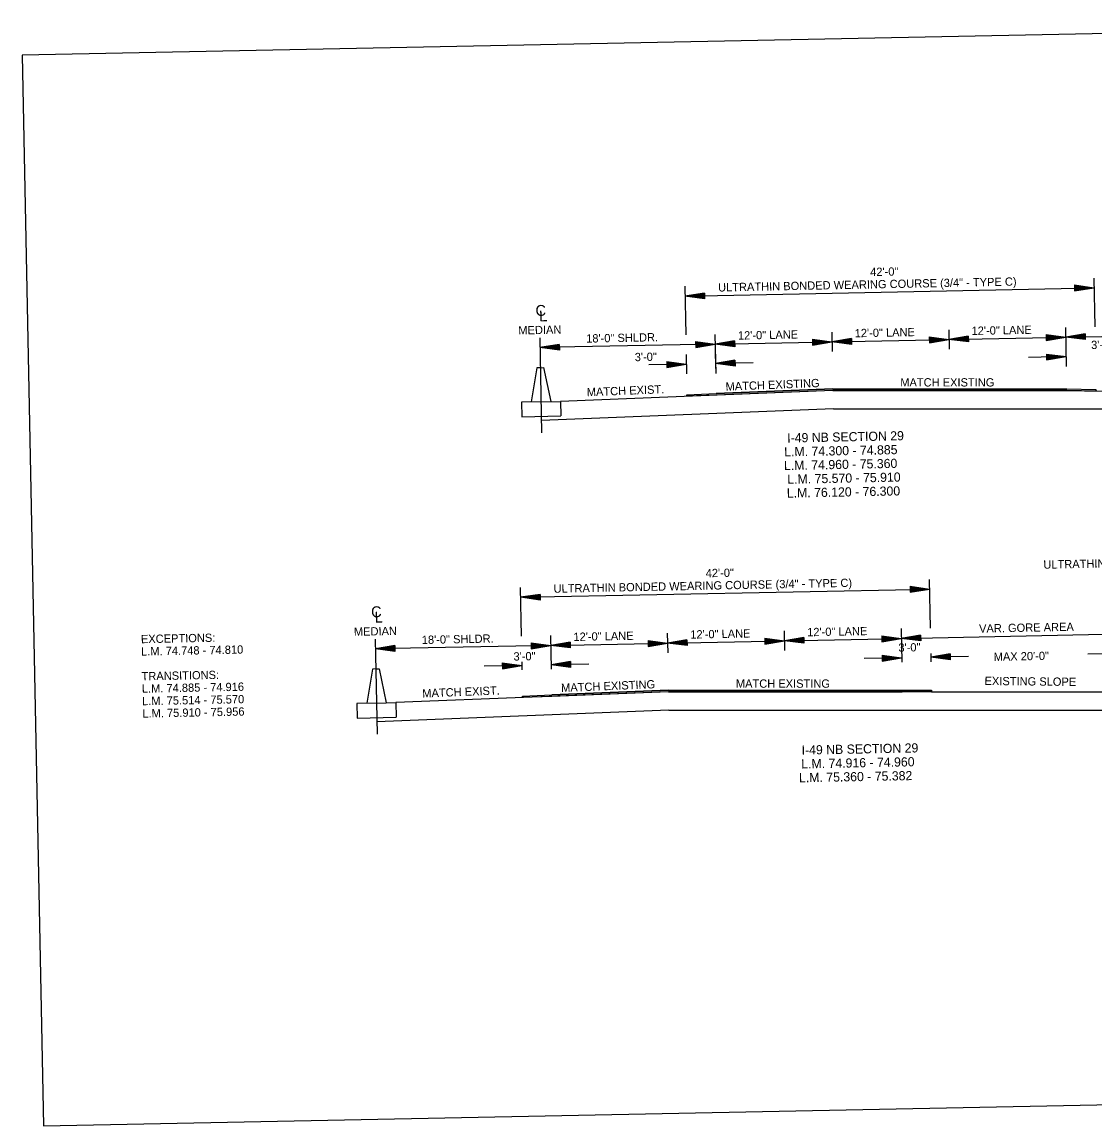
# Model space of a CAD drawing. Extents: x 174 to 869, y -36 to 177.
# Drawn here: x 173.5 to 283.7, y 53.6 to 167 of the extents above; entities that cross this region are included whole.
import ezdxf

# ---------------------------------------------------------------- set-up
doc = ezdxf.new("R2010")
doc.units = 0
for name, color, linetype in [('DSN_DRFT_Common-Annotations', 7, 'Continuous'), ('DSN_DRFT_Common-Line', 7, 'Continuous'), ('DSN_DRFT_Dimension', 7, 'Continuous')]:
    doc.layers.add(name, color=color, linetype=linetype)

msp = doc.modelspace()

# ---------------------------------------------------------------- linework, layer by layer
at = {"layer": 'DSN_DRFT_Common-Line'}
for p, q in [((283.55, 140.68), (283.65, 135.68)), ((241.56, 139.84), (241.66, 134.84)), ((256.66, 135.14), (256.7, 133.14)), ((268.66, 135.38), (268.7, 133.38)), ((280.66, 135.62), (280.74, 131.62)), ((226.67, 134.54), (226.86, 124.79)), ((244.66, 134.9), (244.74, 130.9)), ((241.7, 132.84), (241.74, 130.84)), ((244.7, 132.9), (244.74, 130.9)), ((226.39, 131.47), (225.8, 127.96)), ((226.73, 131.48), (226.39, 131.47)), ((226.73, 131.48), (227.06, 131.49)), ((227.06, 131.49), (227.8, 128)), ((256.78, 129.31), (244.78, 128.83)), ((256.78, 129.31), (280.78, 129.31)), ((256.78, 129.14), (228.8, 128.02)), ((256.78, 129.14), (280.79, 129.14)), ((280.79, 129.14), (290.79, 128.94)), ((226.8, 127.98), (224.8, 127.94)), ((224.8, 127.94), (224.83, 126.44)), ((226.8, 127.98), (228.8, 128.02)), ((256.82, 127.27), (226.84, 126.07)), ((228.8, 128.02), (228.83, 126.52)), ((256.82, 127.27), (302.25, 127.27)), ((224.83, 126.44), (228.83, 126.52)), ((224.68, 108.9), (224.78, 103.9)), ((266.67, 109.74), (266.77, 104.74)), ((251.77, 104.44), (251.81, 102.44)), ((263.77, 104.68), (263.84, 101.22)), ((209.78, 103.6), (209.98, 93.85)), ((227.78, 103.96), (227.85, 100.5)), ((239.77, 104.2), (239.81, 102.2)), ((266.82, 102.12), (266.84, 101.28)), ((224.83, 101.28), (224.85, 100.44)), ((209.51, 100.53), (208.91, 97.02)), ((209.84, 100.54), (209.51, 100.53)), ((209.84, 100.54), (210.17, 100.54)), ((210.17, 100.54), (210.91, 97.06)), ((239.89, 98.2), (211.91, 97.08)), ((239.89, 98.36), (227.9, 97.88)), ((239.89, 98.36), (263.9, 98.36)), ((239.89, 98.2), (263.9, 98.2)), ((266.9, 98.2), (266.9, 98.36)), ((266.9, 98.2), (287.9, 98.2)), ((209.91, 97.04), (207.91, 97)), ((207.91, 97), (207.94, 95.5)), ((209.91, 97.04), (211.91, 97.08)), ((211.91, 97.08), (211.94, 95.58)), ((207.94, 95.5), (211.94, 95.58)), ((239.93, 96.32), (209.95, 95.12)), ((239.93, 96.32), (326.77, 96.32))]:
    msp.add_line(p, q, dxfattribs=at)
for points in [[(173.52, 163.58), (175.72, 53.6), (345.69, 57), (343.49, 166.98)], [(280.79, 129.14), (256.78, 129.14), (244.79, 128.66), (241.79, 128.54), (241.79, 128.71), (244.78, 128.83), (256.78, 129.31), (280.78, 129.31), (283.78, 129.25), (283.79, 129.08)], [(263.9, 98.2), (239.89, 98.2), (227.9, 97.72), (224.9, 97.6), (224.9, 97.76), (227.9, 97.88), (239.89, 98.36), (263.9, 98.36), (266.9, 98.36), (266.9, 98.2)]]:
    msp.add_lwpolyline(points, close=True, dxfattribs=at)
at = {"layer": 'DSN_DRFT_Dimension'}
for p, q in [((241.58, 138.84), (283.57, 139.68)), ((281.57, 139.98), (283.57, 139.68)), ((281.57, 139.98), (281.57, 139.38)), ((281.57, 139.93), (283.24, 139.68)), ((281.57, 139.88), (282.9, 139.68)), ((281.57, 139.83), (282.56, 139.68)), ((281.57, 139.78), (282.22, 139.68)), ((281.57, 139.73), (281.89, 139.68)), ((281.57, 139.38), (283.57, 139.68)), ((281.57, 139.58), (282.22, 139.68)), ((281.57, 139.48), (282.9, 139.68)), ((281.57, 139.43), (283.24, 139.68)), ((281.57, 139.53), (282.56, 139.68)), ((281.57, 139.63), (281.89, 139.68)), ((243.58, 139.14), (241.58, 138.84)), ((243.58, 138.54), (241.58, 138.84)), ((243.58, 139.09), (241.92, 138.84)), ((243.58, 138.59), (241.92, 138.84)), ((243.58, 139.04), (242.26, 138.84)), ((243.58, 138.64), (242.26, 138.84)), ((243.58, 138.99), (242.59, 138.84)), ((243.58, 138.69), (242.59, 138.84)), ((243.58, 138.94), (242.93, 138.84)), ((243.58, 138.74), (242.93, 138.84)), ((243.58, 138.89), (243.27, 138.84)), ((243.58, 138.79), (243.27, 138.84)), ((243.58, 139.14), (243.58, 138.54)), ((282.67, 134.96), (280.68, 134.62)), ((282.67, 134.96), (282.68, 134.36)), ((244.68, 133.9), (226.69, 133.54)), ((228.68, 133.88), (226.69, 133.54)), ((228.68, 133.83), (227.02, 133.55)), ((228.68, 133.88), (228.69, 133.28)), ((242.68, 134.16), (244.68, 133.9)), ((242.68, 134.16), (242.69, 133.56)), ((242.68, 134.11), (244.35, 133.89)), ((242.68, 134.06), (244, 133.89)), ((242.68, 134.01), (243.67, 133.88)), ((242.68, 133.96), (243.33, 133.87)), ((242.68, 133.91), (243, 133.87)), ((242.68, 133.81), (243, 133.87)), ((242.69, 133.56), (244.68, 133.9)), ((242.69, 133.66), (244, 133.89)), ((242.69, 133.61), (244.35, 133.89)), ((242.69, 133.71), (243.67, 133.88)), ((242.69, 133.76), (243.33, 133.87)), ((246.68, 134.24), (244.68, 133.9)), ((244.68, 133.9), (256.68, 134.14)), ((246.69, 133.64), (244.68, 133.9)), ((246.68, 134.19), (245.02, 133.91)), ((246.69, 133.69), (245.02, 133.91)), ((246.68, 134.14), (245.36, 133.91)), ((246.69, 133.74), (245.36, 133.91)), ((246.68, 134.09), (245.69, 133.92)), ((246.69, 133.79), (245.69, 133.92)), ((246.68, 134.04), (246.03, 133.93)), ((246.68, 133.84), (246.03, 133.93)), ((246.68, 133.99), (246.37, 133.93)), ((246.68, 133.89), (246.37, 133.93)), ((246.68, 134.24), (246.69, 133.64)), ((254.67, 134.4), (256.68, 134.14)), ((254.67, 134.4), (254.69, 133.8)), ((254.68, 134.35), (256.35, 134.13)), ((254.68, 134.3), (256, 134.13)), ((254.68, 134.25), (255.67, 134.12)), ((254.68, 134.2), (255.33, 134.11)), ((254.68, 134.15), (255, 134.11)), ((254.68, 133.9), (256, 134.13)), ((254.68, 133.95), (255.67, 134.12)), ((254.68, 134), (255.33, 134.11)), ((254.68, 134.05), (255, 134.11)), ((254.69, 133.8), (256.68, 134.14)), ((254.69, 133.85), (256.35, 134.13)), ((258.67, 134.48), (256.68, 134.14)), ((256.68, 134.14), (268.68, 134.38)), ((258.69, 133.88), (256.68, 134.14)), ((258.67, 134.43), (257.01, 134.15)), ((258.68, 133.93), (257.01, 134.15)), ((258.68, 134.38), (257.36, 134.15)), ((258.68, 133.98), (257.36, 134.15)), ((258.68, 134.33), (257.69, 134.16)), ((258.68, 134.03), (257.69, 134.16)), ((258.68, 134.28), (258.03, 134.17)), ((258.68, 134.08), (258.03, 134.17)), ((258.68, 134.23), (258.36, 134.17)), ((258.68, 134.13), (258.36, 134.17)), ((258.67, 134.48), (258.69, 133.88)), ((266.67, 134.64), (268.68, 134.38)), ((266.67, 134.64), (266.68, 134.04)), ((266.67, 134.59), (268.34, 134.37)), ((266.67, 134.54), (268, 134.37)), ((266.68, 134.49), (267.67, 134.36)), ((266.68, 134.44), (267.33, 134.35)), ((266.68, 134.39), (266.99, 134.35)), ((266.68, 134.04), (268.68, 134.38)), ((266.68, 134.14), (268, 134.37)), ((266.68, 134.09), (268.34, 134.37)), ((266.68, 134.19), (267.67, 134.36)), ((266.68, 134.24), (267.33, 134.35)), ((266.68, 134.29), (266.99, 134.35)), ((270.67, 134.72), (268.68, 134.38)), ((268.68, 134.38), (280.68, 134.62)), ((270.68, 134.12), (268.68, 134.38)), ((270.67, 134.67), (269.01, 134.39)), ((270.68, 134.17), (269.01, 134.39)), ((270.67, 134.62), (269.36, 134.39)), ((270.68, 134.22), (269.36, 134.39)), ((270.67, 134.57), (269.69, 134.4)), ((270.68, 134.27), (269.69, 134.4)), ((270.68, 134.52), (270.03, 134.41)), ((270.68, 134.32), (270.03, 134.41)), ((270.68, 134.47), (270.36, 134.41)), ((270.68, 134.37), (270.36, 134.41)), ((270.67, 134.72), (270.68, 134.12)), ((278.67, 134.88), (280.68, 134.62)), ((278.67, 134.88), (278.68, 134.28)), ((278.67, 134.83), (280.34, 134.61)), ((278.67, 134.78), (280, 134.61)), ((278.67, 134.73), (279.66, 134.6)), ((278.67, 134.68), (279.33, 134.59)), ((278.68, 134.63), (278.99, 134.59)), ((278.68, 134.28), (280.68, 134.62)), ((278.68, 134.38), (280, 134.61)), ((278.68, 134.33), (280.34, 134.61)), ((278.68, 134.43), (279.66, 134.6)), ((278.68, 134.48), (279.33, 134.59)), ((278.68, 134.53), (278.99, 134.59)), ((280.68, 134.62), (290.67, 134.82)), ((282.68, 134.36), (280.68, 134.62)), ((282.67, 134.91), (281.01, 134.63)), ((282.68, 134.41), (281.01, 134.63)), ((282.67, 134.86), (281.35, 134.63)), ((282.68, 134.46), (281.35, 134.63)), ((282.67, 134.81), (281.69, 134.64)), ((282.68, 134.51), (281.69, 134.64)), ((282.67, 134.76), (282.03, 134.65)), ((282.68, 134.56), (282.03, 134.65)), ((282.67, 134.71), (282.36, 134.65)), ((282.68, 134.61), (282.36, 134.65)), ((228.69, 133.28), (226.69, 133.54)), ((228.69, 133.33), (227.02, 133.55)), ((228.68, 133.78), (227.36, 133.55)), ((228.69, 133.38), (227.36, 133.55)), ((228.68, 133.73), (227.7, 133.56)), ((228.69, 133.43), (227.7, 133.56)), ((228.68, 133.68), (228.04, 133.57)), ((228.69, 133.48), (228.04, 133.57)), ((228.69, 133.63), (228.37, 133.57)), ((228.69, 133.53), (228.37, 133.57)), ((278.71, 132.88), (280.72, 132.62)), ((278.71, 132.88), (278.72, 132.28)), ((278.71, 132.83), (280.38, 132.61)), ((278.71, 132.78), (280.04, 132.61)), ((278.71, 132.73), (279.7, 132.6)), ((278.71, 132.68), (279.37, 132.59)), ((241.72, 131.84), (237.86, 131.76)), ((239.72, 132.1), (241.72, 131.84)), ((239.72, 132.1), (239.73, 131.5)), ((239.72, 132.05), (241.39, 131.83)), ((239.72, 132), (241.05, 131.83)), ((239.72, 131.95), (240.71, 131.82)), ((239.72, 131.9), (240.37, 131.81)), ((239.72, 131.85), (240.04, 131.81)), ((239.72, 131.75), (240.04, 131.81)), ((239.73, 131.5), (241.72, 131.84)), ((239.73, 131.6), (241.05, 131.83)), ((239.73, 131.55), (241.39, 131.83)), ((239.73, 131.65), (240.71, 131.82)), ((239.73, 131.7), (240.37, 131.81)), ((246.72, 132.24), (244.72, 131.9)), ((248.59, 131.98), (244.72, 131.9)), ((246.73, 131.64), (244.72, 131.9)), ((246.72, 132.19), (245.06, 131.91)), ((246.73, 131.69), (245.06, 131.91)), ((246.72, 132.14), (245.4, 131.91)), ((246.73, 131.74), (245.4, 131.91)), ((246.72, 132.09), (245.73, 131.92)), ((246.73, 131.79), (245.73, 131.92)), ((246.72, 132.04), (246.07, 131.93)), ((246.72, 131.84), (246.07, 131.93)), ((246.72, 131.99), (246.41, 131.93)), ((246.72, 131.89), (246.41, 131.93)), ((246.72, 132.24), (246.73, 131.64)), ((280.72, 132.62), (276.85, 132.54)), ((278.72, 132.63), (279.03, 132.59)), ((278.72, 132.28), (280.72, 132.62)), ((278.72, 132.38), (280.04, 132.61)), ((278.72, 132.33), (280.38, 132.61)), ((278.72, 132.43), (279.7, 132.6)), ((278.72, 132.48), (279.37, 132.59)), ((278.72, 132.53), (279.03, 132.59)), ((264.69, 109.04), (266.69, 108.74)), ((264.69, 109.04), (264.69, 108.44)), ((264.69, 108.99), (266.35, 108.74)), ((264.69, 108.93), (266.01, 108.74)), ((264.69, 108.88), (265.68, 108.74)), ((224.7, 107.9), (266.69, 108.74)), ((226.7, 108.2), (224.7, 107.9)), ((226.7, 107.6), (224.7, 107.9)), ((226.7, 108.15), (225.03, 107.9)), ((226.7, 107.65), (225.03, 107.9)), ((226.7, 108.09), (225.38, 107.9)), ((226.7, 107.7), (225.38, 107.9)), ((226.7, 108.04), (225.71, 107.9)), ((226.7, 107.75), (225.71, 107.9)), ((226.7, 107.99), (226.05, 107.9)), ((226.7, 107.8), (226.05, 107.9)), ((226.7, 107.94), (226.38, 107.9)), ((226.7, 107.85), (226.38, 107.9)), ((226.7, 108.2), (226.7, 107.6)), ((264.69, 108.83), (265.34, 108.74)), ((264.69, 108.78), (265, 108.74)), ((264.69, 108.44), (266.69, 108.74)), ((264.69, 108.64), (265.34, 108.74)), ((264.69, 108.54), (266.01, 108.74)), ((264.69, 108.49), (266.35, 108.74)), ((264.69, 108.59), (265.68, 108.74)), ((264.69, 108.69), (265, 108.74)), ((225.79, 103.22), (227.8, 102.96)), ((225.79, 103.22), (225.8, 102.62)), ((229.79, 103.3), (227.8, 102.96)), ((227.8, 102.96), (239.79, 103.2)), ((229.79, 103.25), (228.13, 102.96)), ((229.79, 103.2), (228.47, 102.97)), ((229.79, 103.3), (229.8, 102.7)), ((237.79, 103.46), (239.79, 103.2)), ((237.79, 103.46), (237.8, 102.86)), ((237.79, 103.41), (239.46, 103.19)), ((237.79, 103.36), (239.12, 103.18)), ((237.79, 103.31), (238.78, 103.18)), ((237.79, 103.25), (238.44, 103.17)), ((237.79, 103.2), (238.11, 103.16)), ((237.8, 102.86), (239.79, 103.2)), ((237.8, 102.91), (239.46, 103.19)), ((237.8, 102.96), (239.12, 103.18)), ((237.8, 103.01), (238.78, 103.18)), ((241.79, 103.54), (239.79, 103.2)), ((239.79, 103.2), (251.79, 103.44)), ((241.8, 102.94), (239.79, 103.2)), ((241.79, 103.49), (240.13, 103.2)), ((241.8, 102.99), (240.13, 103.2)), ((241.79, 103.44), (240.47, 103.21)), ((241.8, 103.04), (240.47, 103.21)), ((241.79, 103.39), (240.8, 103.22)), ((241.8, 103.09), (240.8, 103.22)), ((241.79, 103.33), (241.14, 103.22)), ((241.8, 103.14), (241.14, 103.22)), ((241.79, 103.28), (241.48, 103.23)), ((241.79, 103.19), (241.48, 103.23)), ((241.79, 103.54), (241.8, 102.94)), ((249.79, 103.7), (251.79, 103.44)), ((249.79, 103.7), (249.8, 103.1)), ((249.79, 103.65), (251.46, 103.43)), ((249.79, 103.6), (251.11, 103.42)), ((249.79, 103.55), (250.78, 103.42)), ((249.79, 103.49), (250.44, 103.41)), ((249.79, 103.44), (250.11, 103.4)), ((249.79, 103.3), (250.44, 103.41)), ((249.79, 103.35), (250.11, 103.4)), ((249.8, 103.1), (251.79, 103.44)), ((249.8, 103.15), (251.46, 103.43)), ((249.8, 103.2), (251.11, 103.42)), ((249.8, 103.25), (250.78, 103.42)), ((253.79, 103.78), (251.79, 103.44)), ((251.79, 103.44), (263.79, 103.68)), ((253.8, 103.18), (251.79, 103.44)), ((253.79, 103.73), (252.13, 103.44)), ((253.8, 103.23), (252.13, 103.44)), ((253.79, 103.68), (252.47, 103.45)), ((253.8, 103.28), (252.47, 103.45)), ((253.79, 103.63), (252.8, 103.46)), ((253.79, 103.33), (252.8, 103.46)), ((253.79, 103.57), (253.14, 103.46)), ((253.79, 103.38), (253.14, 103.46)), ((253.79, 103.52), (253.48, 103.47)), ((253.79, 103.43), (253.48, 103.47)), ((253.79, 103.78), (253.8, 103.18)), ((261.78, 103.94), (263.79, 103.68)), ((261.78, 103.94), (261.8, 103.34)), ((261.78, 103.89), (263.46, 103.67)), ((261.79, 103.84), (263.11, 103.66)), ((261.79, 103.79), (262.78, 103.66)), ((261.79, 103.73), (262.44, 103.65)), ((261.79, 103.68), (262.11, 103.64)), ((261.79, 103.39), (263.46, 103.67)), ((261.79, 103.44), (263.11, 103.66)), ((261.79, 103.49), (262.78, 103.66)), ((261.79, 103.54), (262.44, 103.65)), ((261.79, 103.59), (262.11, 103.64)), ((261.8, 103.34), (263.79, 103.68)), ((263.79, 103.68), (288.78, 104.18)), ((265.78, 104.02), (263.79, 103.68)), ((265.79, 103.42), (263.79, 103.68)), ((265.78, 103.97), (264.12, 103.68)), ((265.79, 103.47), (264.12, 103.68)), ((265.78, 103.92), (264.47, 103.69)), ((265.79, 103.52), (264.47, 103.69)), ((265.79, 103.87), (264.8, 103.7)), ((265.79, 103.57), (264.8, 103.7)), ((265.79, 103.81), (265.14, 103.7)), ((265.79, 103.62), (265.14, 103.7)), ((265.79, 103.76), (265.47, 103.71)), ((265.79, 103.67), (265.47, 103.71)), ((265.78, 104.02), (265.79, 103.42)), ((227.8, 102.96), (209.8, 102.6)), ((211.79, 102.94), (209.8, 102.6)), ((211.81, 102.34), (209.8, 102.6)), ((211.79, 102.89), (210.13, 102.6)), ((211.8, 102.39), (210.13, 102.6)), ((211.8, 102.84), (210.48, 102.61)), ((211.8, 102.44), (210.48, 102.61)), ((211.8, 102.79), (210.81, 102.62)), ((211.8, 102.49), (210.81, 102.62)), ((211.8, 102.73), (211.15, 102.62)), ((211.8, 102.54), (211.15, 102.62)), ((211.8, 102.68), (211.48, 102.63)), ((211.8, 102.59), (211.48, 102.63)), ((211.79, 102.94), (211.81, 102.34)), ((225.79, 103.17), (227.46, 102.95)), ((225.79, 103.12), (227.12, 102.94)), ((225.79, 103.07), (226.79, 102.94)), ((225.79, 103.01), (226.45, 102.93)), ((225.8, 102.62), (227.8, 102.96)), ((225.8, 102.96), (226.11, 102.92)), ((225.8, 102.67), (227.46, 102.95)), ((225.8, 102.72), (227.12, 102.94)), ((225.8, 102.77), (226.79, 102.94)), ((225.8, 102.82), (226.45, 102.93)), ((225.8, 102.87), (226.11, 102.92)), ((229.8, 102.7), (227.8, 102.96)), ((229.8, 102.75), (228.13, 102.96)), ((229.8, 102.8), (228.47, 102.97)), ((229.79, 103.15), (228.81, 102.98)), ((229.8, 102.85), (228.81, 102.98)), ((229.79, 103.09), (229.15, 102.98)), ((229.8, 102.9), (229.15, 102.98)), ((229.8, 103.04), (229.48, 102.99)), ((229.8, 102.95), (229.48, 102.99)), ((237.8, 103.06), (238.44, 103.17)), ((237.8, 103.11), (238.11, 103.16)), ((268.82, 102.08), (266.83, 101.74)), ((268.82, 102.08), (268.83, 101.48)), ((286.82, 102.14), (282.96, 102.06)), ((222.83, 101.16), (224.84, 100.9)), ((222.83, 101.16), (222.84, 100.56)), ((222.83, 101.11), (224.5, 100.89)), ((222.83, 101.06), (224.16, 100.88)), ((222.83, 101.01), (223.83, 100.88)), ((222.84, 100.95), (223.49, 100.87)), ((229.83, 101.3), (227.84, 100.96)), ((231.7, 101.03), (227.84, 100.96)), ((229.84, 100.7), (227.84, 100.96)), ((229.83, 101.25), (228.17, 100.96)), ((229.84, 100.75), (228.17, 100.96)), ((229.83, 101.2), (228.51, 100.97)), ((229.84, 100.8), (228.51, 100.97)), ((229.83, 101.15), (228.85, 100.98)), ((229.84, 100.85), (228.85, 100.98)), ((229.83, 101.09), (229.19, 100.98)), ((229.84, 100.9), (229.19, 100.98)), ((229.84, 101.04), (229.52, 100.99)), ((229.84, 100.95), (229.52, 100.99)), ((229.83, 101.3), (229.84, 100.7)), ((263.83, 101.68), (259.97, 101.6)), ((261.82, 101.94), (263.83, 101.68)), ((261.82, 101.94), (261.84, 101.34)), ((261.82, 101.89), (263.5, 101.67)), ((261.83, 101.84), (263.15, 101.66)), ((261.83, 101.79), (262.82, 101.66)), ((261.83, 101.73), (262.48, 101.65)), ((261.83, 101.68), (262.15, 101.64)), ((261.83, 101.39), (263.5, 101.67)), ((261.83, 101.44), (263.15, 101.66)), ((261.83, 101.49), (262.82, 101.66)), ((261.83, 101.54), (262.48, 101.65)), ((261.83, 101.59), (262.15, 101.64)), ((261.84, 101.34), (263.83, 101.68)), ((270.69, 101.81), (266.83, 101.74)), ((268.83, 101.48), (266.83, 101.74)), ((268.82, 102.03), (267.16, 101.74)), ((268.83, 101.53), (267.16, 101.74)), ((268.82, 101.98), (267.51, 101.75)), ((268.83, 101.58), (267.51, 101.75)), ((268.83, 101.93), (267.84, 101.76)), ((268.83, 101.63), (267.84, 101.76)), ((268.83, 101.87), (268.18, 101.76)), ((268.83, 101.68), (268.18, 101.76)), ((268.83, 101.82), (268.51, 101.77)), ((268.83, 101.73), (268.51, 101.77)), ((224.84, 100.9), (220.97, 100.82)), ((222.84, 100.56), (224.84, 100.9)), ((222.84, 100.9), (223.15, 100.86)), ((222.84, 100.61), (224.5, 100.89)), ((222.84, 100.66), (224.16, 100.88)), ((222.84, 100.71), (223.83, 100.88)), ((222.84, 100.76), (223.49, 100.87)), ((222.84, 100.81), (223.15, 100.86))]:
    msp.add_line(p, q, dxfattribs=at)

# ---------------------------------------------------------------- texts
at = {"layer": 'DSN_DRFT_Common-Annotations'}
for s, height, rotation, p in [('42\'-0"', 0.85, 1.1458, (260.61, 140.89)), ('ULTRATHIN BONDED WEARING COURSE (3/4" - TYPE C)', 0.85, 1.1458, (244.99, 139.3)), ('C', 1.12, 2.2915, (226.26, 136.78)), ('L', 1.12, 2.2915, (226.63, 136.22)), ('MEDIAN', 0.85, 1.1458, (224.48, 134.89)), ('18\'-0" SHLDR.', 0.85, 1.1458, (231.45, 134.05)), ('12\'-0" LANE', 0.85, 1.1458, (247.03, 134.36)), ('12\'-0" LANE', 0.85, 1.1458, (259.02, 134.6)), ('12\'-0" LANE', 0.85, 1.1458, (271.02, 134.84)), (' 3\'-0"', 0.85, 1.1458, (282.98, 133.39)), (' 3\'-0"', 0.85, 1.1458, (236.12, 132.14)), ('MATCH EXIST.', 0.85, 2.2915, (231.52, 128.54)), ('MATCH EXISTING', 0.85, 2.2915, (245.77, 129.11)), ('I-49 NB SECTION 29', 0.943, 1.1458, (252.09, 123.79)), ('L.M. 74.300 - 74.885', 0.943, 1.1458, (251.78, 122.37)), ('L.M. 74.960 - 75.360', 0.943, 1.1458, (251.76, 120.96)), ('L.M. 75.570 - 75.910', 0.943, 1.1458, (252.1, 119.55)), ('L.M. 76.120 - 76.300', 0.943, 1.1458, (252.05, 118.13)), ('ULTRATHIN BONDED WEARING COURSE (3/4" - TYPE C)', 0.85, 1.1458, (278.39, 110.83)), ('42\'-0"', 0.85, 1.1458, (243.72, 109.95)), ('ULTRATHIN BONDED WEARING COURSE (3/4" - TYPE C)', 0.85, 1.1458, (228.1, 108.36)), ('C', 1.12, 2.2915, (209.38, 105.83)), ('L', 1.12, 2.2915, (209.74, 105.28)), ('MEDIAN', 0.85, 1.1458, (207.6, 103.94)), ('12\'-0" LANE', 0.85, 1.1458, (230.14, 103.41)), ('12\'-0" LANE', 0.85, 1.1458, (242.14, 103.65)), ('12\'-0" LANE', 0.85, 1.1458, (254.14, 103.89)), ('VAR. GORE AREA', 0.85, 1.1458, (271.79, 104.26)), ('EXCEPTIONS:', 0.85, 1.1458, (185.73, 103.18)), ('18\'-0" SHLDR.', 0.85, 1.1458, (214.57, 103.1)), (' 3\'-0"', 0.85, 1.1458, (263.19, 102.3)), ('L.M. 74.748 - 74.810', 0.85, 1.1458, (185.75, 101.91)), (' 3\'-0"', 0.85, 1.1458, (223.67, 101.39)), ('MAX 20\'-0"', 0.85, 1.1458, (273.29, 101.36)), ('TRANSITIONS:', 0.85, 1.1458, (185.8, 99.36)), ('L.M. 74.885 - 74.916', 0.85, 1.1458, (185.83, 98.09)), ('MATCH EXIST.', 0.85, 2.2915, (214.63, 97.6)), ('MATCH EXISTING', 0.85, 2.2915, (228.88, 98.17)), ('EXISTING SLOPE', 0.85, 359.3769, (272.34, 98.89)), ('L.M. 75.514 - 75.570', 0.85, 1.1458, (185.85, 96.81)), ('L.M. 75.910 - 75.956', 0.85, 1.1458, (185.88, 95.54)), ('I-49 NB SECTION 29', 0.943, 1.1458, (253.57, 91.73)), ('L.M. 74.916 - 74.960', 0.943, 1.1458, (253.53, 90.31)), ('L.M. 75.360 - 75.382', 0.943, 1.1458, (253.3, 88.89))]:
    msp.add_text(s, height=height, rotation=rotation, dxfattribs=at).set_placement(p)
for p in [(263.69, 129.55), (246.81, 98.61)]:
    msp.add_text('MATCH EXISTING', height=0.85, dxfattribs=at).set_placement(p)

doc.saveas('drawing.dxf')
